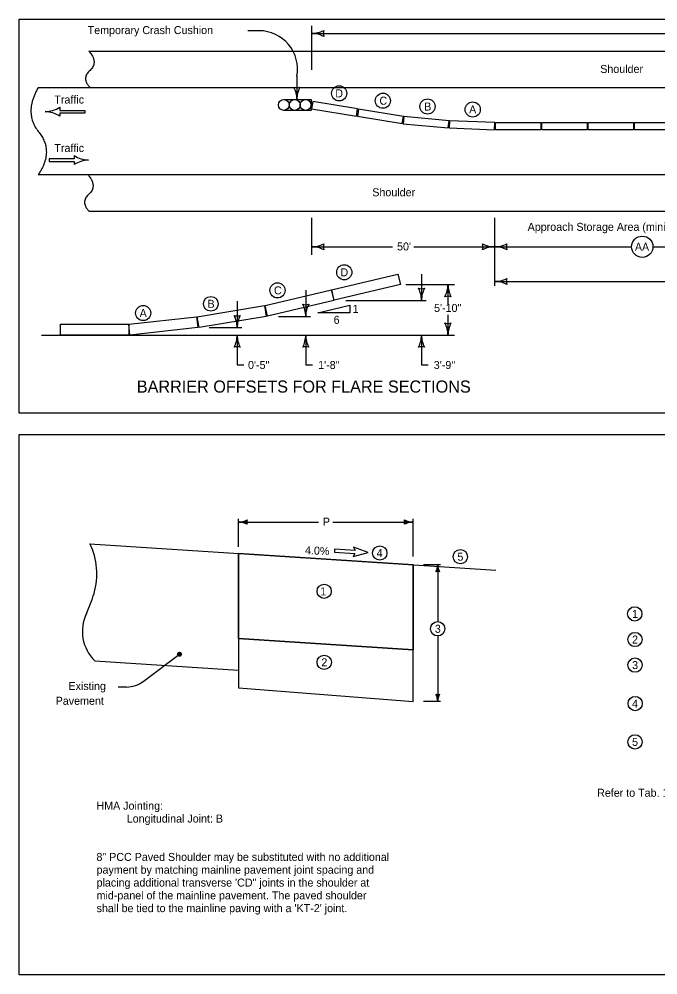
# Model space of a CAD drawing. Extents: x 6410 to 81668, y 3928 to 11667.
# Drawn here: x 13752 to 14807, y 3928 to 5504 of the extents above; entities that cross this region are included whole.
import ezdxf

# ---------------------------------------------------------------- set-up
doc = ezdxf.new("R2010")
doc.units = 0
doc.layers.add('dsnStdSection', color=7, linetype='Continuous')

msp = doc.modelspace()

# ---------------------------------------------------------------- linework, layer by layer
at = {"layer": 'dsnStdSection'}
for p, q in [((13752.2, 5504.3), (16857.2, 5504.3)), ((13752.2, 4854.3), (13752.2, 5504.3)), ((14235.1, 5493.4), (14235.1, 5420.9)), ((14148.6, 5485.1), (14129.9, 5485.1)), ((14235.1, 5480.7), (15168, 5480.7)), ((13867.5, 5451.7), (14996, 5451.7)), ((14210.8, 5410.5), (14210.8, 5371.8)), ((13783.9, 5391.7), (15026, 5391.7)), ((14189.2, 5371.8), (14234.2, 5371.8)), ((14234.2, 5371.8), (14234.2, 5353.8)), ((13795.4, 5351.6), (13795.4, 5351.6)), ((13819.3, 5359.1), (13819.3, 5353.8)), ((13819.3, 5353.8), (13860.5, 5353.8)), ((13860.5, 5349.3), (13819.3, 5349.3)), ((13819.3, 5349.3), (13819.3, 5344.1)), ((13860.5, 5353.8), (13860.5, 5349.3)), ((14234.2, 5353.8), (14189.2, 5353.8)), ((14233, 5359.5), (14234.3, 5359.2)), ((14234.8, 5355.8), (14234.8, 5355.8)), ((13842.9, 5274), (13801.7, 5274)), ((13801.7, 5274), (13801.7, 5269.5)), ((13801.7, 5269.5), (13842.9, 5269.5)), ((13842.9, 5279.2), (13842.9, 5274)), ((13842.9, 5269.5), (13842.9, 5264.2)), ((13866.8, 5271.7), (13866.8, 5271.7)), ((13783.9, 5247.7), (15026, 5247.7)), ((13867.5, 5187.7), (14996, 5187.7)), ((14235.1, 5176.4), (14235.1, 5115.2)), ((14537.3, 5176.4), (14537.3, 5064.1)), ((14235.1, 5128.7), (14368.5, 5128.7)), ((14403.8, 5128.7), (14537.3, 5128.7)), ((14537.3, 5128.7), (14763.4, 5128.7)), ((14798.7, 5128.7), (15024.8, 5128.7)), ((14416.5, 5083.8), (14416.5, 5040.3)), ((14390.6, 5066.3), (14471, 5066.3)), ((14460.2, 5066.3), (14460.2, 5032.8)), ((14537.3, 5071.5), (15128.1, 5071.5)), ((14225.4, 5057.4), (14225.4, 5013.9)), ((14112.2, 5038.8), (14112.2, 4995.3)), ((14245.5, 5019.9), (14298.1, 5032.4)), ((14291.7, 5040.3), (14424.3, 5040.3)), ((14298.1, 5032.4), (14298.1, 5019.9)), ((14298.1, 5019.9), (14245.5, 5019.9)), ((14460.2, 5016.5), (14460.2, 4983)), ((14180.4, 5013.9), (14233.1, 5013.9)), ((13789.1, 4983), (14471, 4983)), ((14066.2, 4995.3), (14119.9, 4995.3)), ((14112.2, 4983), (14112.2, 4956.1)), ((14225.4, 4983), (14225.4, 4933.7)), ((14416.5, 4983), (14416.5, 4933.7)), ((14112.2, 4956.1), (14112.2, 4933.7)), ((14112.2, 4933.7), (14123.3, 4933.7)), ((14225.4, 4933.7), (14236.5, 4933.7)), ((14416.5, 4933.7), (14427.7, 4933.7)), ((16857.2, 4854.3), (13752.2, 4854.3)), ((14114.2, 4633.9), (14114.2, 4680.1)), ((14114.2, 4674.5), (14128, 4674.5)), ((14114.2, 4674.5), (14246.5, 4674.5)), ((14270.4, 4674.5), (14402.7, 4674.5)), ((14402.7, 4674.5), (14388.8, 4674.5)), ((14402.7, 4617.8), (14402.7, 4680.1)), ((13868.8, 4638.8), (14539.1, 4595.4)), ((14420, 4604.3), (14448, 4604.3)), ((14443.3, 4604.3), (14443.3, 4592.8)), ((14443.3, 4604.3), (14443.3, 4510.3)), ((14114.2, 4482.6), (14402.7, 4463.9)), ((14443.3, 4486.7), (14443.3, 4378.7)), ((13957, 4411.7), (14017.1, 4456.7)), ((13877, 4445.5), (14114.2, 4430.2)), ((13929.6, 4402.4), (13915.5, 4402.4)), ((14443.3, 4378.7), (14443.3, 4390.1)), ((14448, 4378.7), (14420, 4378.7))]:
    msp.add_line(p, q, dxfattribs=at)
for points in [[(14311.1, 5356.3), (14237, 5368.4), (14235.1, 5356.5), (14309.1, 5344.4)], [(14386.6, 5343.9), (14312.5, 5356), (14310.6, 5344.2), (14384.6, 5332)], [(14462, 5336.6), (14387.3, 5343.8), (14386.2, 5331.8), (14460.8, 5324.7)], [(14537.7, 5333.7), (14462.8, 5336.7), (14462.3, 5324.7), (14537.3, 5321.7)], [(14538.5, 5333.7), (14613.5, 5333.7), (14613.5, 5321.7), (14538.5, 5321.7)], [(14615, 5333.7), (14690, 5333.7), (14690, 5321.7), (14615, 5321.7)], [(14691.5, 5333.7), (14766.5, 5333.7), (14766.5, 5321.7), (14691.5, 5321.7)], [(14768, 5333.7), (14843, 5333.7), (14843, 5321.7), (14768, 5321.7)], [(14268.2, 5057.9), (14377.7, 5083.8), (14381.8, 5066.3), (14272.3, 5040.4)], [(14158.4, 5031.9), (14267.8, 5057.8), (14272, 5040.3), (14162.5, 5014.4)], [(14046.3, 5013.2), (14157.3, 5031.7), (14160.2, 5013.9), (14049.2, 4995.5)], [(13820.7, 5001.1), (13933.2, 5001), (13933.2, 4983), (13820.7, 4983.1)], [(13933.2, 5000.9), (14045, 5013.2), (14047, 4995.3), (13935.2, 4983)], [(13752.2, 4818.8), (15302.9, 4818.8), (15302.9, 3927.5), (13752.2, 3927.5)], [(14114.2, 4623.2), (14402.7, 4604.3), (14402.7, 4463.9), (14114.2, 4482.6)], [(14303.5, 4617.9), (14328.4, 4624.1), (14304.3, 4633.1), (14307, 4627.9), (14273.1, 4630.1), (14272.8, 4624.9), (14306.6, 4622.8)]]:
    msp.add_lwpolyline(points, close=True, dxfattribs=at)
for points in [[(14127.8, 4672), (14127.2, 4674.5), (14127.8, 4677.1), (14124.7, 4675.6), (14119.8, 4674.5), (14125, 4673.3), (14127.3, 4672.3), (14126.8, 4674.5), (14127, 4676.2), (14124.9, 4675.2), (14122.2, 4674.5), (14125.1, 4673.7), (14126.6, 4673.2), (14126.3, 4675.4), (14124.3, 4674.5), (14125.9, 4674), (14125.9, 4674.8), (14125.2, 4674.6)], [(14389.1, 4677.1), (14389.6, 4674.5), (14389.1, 4671.9), (14392.2, 4673.4), (14397.1, 4674.5), (14391.8, 4675.7), (14389.6, 4676.8), (14390.1, 4674.5), (14389.9, 4672.9), (14391.9, 4673.8), (14394.7, 4674.5), (14391.8, 4675.4), (14390.3, 4675.9), (14390.5, 4673.7), (14392.5, 4674.5), (14391, 4675), (14390.9, 4674.3), (14391.7, 4674.5)], [(14114.2, 4623.2), (14114.2, 4401.3), (14402.7, 4378.7), (14402.7, 4604.3)], [(14441.2, 4593.1), (14443.4, 4593.5), (14445.5, 4593.1), (14444.3, 4595.6), (14443.4, 4599.7), (14442.3, 4595.3), (14441.5, 4593.4), (14443.4, 4593.9), (14444.7, 4593.7), (14443.9, 4595.4), (14443.4, 4597.6), (14442.7, 4595.3), (14442.2, 4594), (14444.1, 4594.2), (14443.4, 4595.9), (14442.9, 4594.6), (14443.6, 4594.6), (14443.4, 4595.2)], [(14019.1, 4458.3), (14018, 4458.7), (14016.4, 4459.5), (14015, 4458.6), (14014.2, 4457.4), (14013.9, 4455.7), (14015.1, 4454.7), (14016.5, 4453.7), (14018, 4454), (14019.1, 4454.9), (14019.7, 4456.9), (14018.9, 4457.9), (14017.5, 4458.7), (14015.7, 4458.9), (14014.7, 4457.8), (14014.5, 4456.1), (14015.5, 4455), (14016.9, 4454.1), (14017.7, 4454.5), (14018.7, 4455.1), (14019.2, 4456.6), (14018.3, 4457.4), (14017.1, 4458.3), (14015.9, 4458.4), (14015.3, 4457.1), (14015.4, 4455.8), (14016.4, 4454.8), (14017.2, 4455), (14018.1, 4455.3), (14018.4, 4456.6), (14017.8, 4457.5), (14016.8, 4457.8), (14016.1, 4457.1), (14015.9, 4456.3), (14016.4, 4455.4), (14017, 4455.4), (14017.5, 4455.6), (14017.8, 4456.5), (14017.4, 4457.1), (14016.7, 4457.3), (14016.4, 4456.8), (14016.5, 4456.2), (14017, 4455.8), (14017.3, 4456.1), (14017.1, 4456.7)], [(14445.5, 4389.9), (14443.3, 4389.5), (14441.2, 4389.9), (14442.4, 4387.4), (14443.3, 4383.3), (14444.4, 4387.7), (14445.2, 4389.5), (14443.3, 4389.1), (14442, 4389.2), (14442.8, 4387.6), (14443.3, 4385.3), (14444, 4387.7), (14444.5, 4389), (14442.6, 4388.7), (14443.3, 4387.1), (14443.7, 4388.4), (14443.1, 4388.4), (14443.3, 4387.8)]]:
    msp.add_lwpolyline(points, dxfattribs=at)
for centre, radius in [((14280.6, 5381.8), 12.5), ((14352.8, 5369.7), 12.5), ((14189.2, 5362.8), 9), ((14189.2, 5362.8), 9), ((14207.2, 5362.8), 9), ((14207.2, 5362.8), 9), ((14225.2, 5362.8), 9), ((14225.2, 5362.8), 9), ((14426.5, 5360.1), 12.5), ((14501.1, 5355.2), 12.5), ((14781, 5128.7), 17.6), ((14289, 5086.6), 12.5), ((14178.7, 5056.8), 12.5), ((14068.7, 5034.6), 12.2), ((13957.1, 5019.4), 12.5), ((14347.7, 4623.5), 11.8), ((14480.7, 4617.4), 11.8), ((14255.8, 4560.4), 11.8), ((14768.6, 4523.1), 11.8), ((14443.3, 4498.5), 11.8), ((14768.9, 4480.8), 11.8), ((14016.9, 4456.5), 3.15), ((14255.9, 4443.2), 11.8), ((14769.1, 4438.6), 11.8), ((14769.3, 4375.2), 11.8), ((14769, 4311.9), 11.8)]:
    msp.add_circle(centre, radius, dxfattribs=at)
for centre, radius, start, end in [((14148.6, 5421.8), 63.3, 349.6463, 90), ((14235.1, 5523.2), 42.5, 270, 298.0725), ((14235.1, 5438.2), 42.5, 61.9275, 90), ((14270.7, 5480.7), 16.4, 162.2666, 197.7334), ((14210.8, 5407.5), 16.4, 252.2666, 287.7333), ((14168.3, 5371.8), 42.5, 360, 28.0725), ((14253.3, 5371.8), 42.5, 151.9275, 180), ((13793.4, 5399.9), 48.4, 272.352, 302.382), ((13793.4, 5303.3), 48.4, 57.618, 87.648), ((13868.8, 5320.1), 48.4, 237.618, 267.648), ((13868.8, 5223.4), 48.4, 92.352, 122.382), ((14235.1, 5171.2), 42.5, 270, 298.0725), ((14235.1, 5086.2), 42.5, 61.9275, 90), ((14270.7, 5128.7), 16.4, 162.2666, 197.7334), ((14501.6, 5128.7), 16.4, 342.2666, 17.7333), ((14537.3, 5171.2), 42.5, 241.9275, 270), ((14537.3, 5086.2), 42.5, 90, 118.0725), ((14537.3, 5171.2), 42.5, 270, 298.0725), ((14537.3, 5086.2), 42.5, 61.9275, 90), ((14572.9, 5128.7), 16.4, 162.2666, 197.7334), ((14417.7, 5066.3), 42.5, 331.9275, 360), ((14502.7, 5066.3), 42.5, 180, 208.0725), ((14537.3, 5114), 42.5, 270, 298.0725), ((14537.3, 5029), 42.5, 61.9275, 90), ((14572.9, 5071.5), 16.4, 162.2666, 197.7334), ((14416.5, 5075.9), 16.4, 252.2666, 287.7333), ((14374, 5040.3), 42.5, 360, 28.0725), ((14459, 5040.3), 42.5, 151.9275, 180), ((14460.2, 5030.7), 16.4, 72.2666, 107.7334), ((14225.4, 5049.5), 16.4, 252.2666, 287.7333), ((14182.9, 5013.9), 42.5, 360, 28.0725), ((14267.9, 5013.9), 42.5, 151.9275, 180), ((14112.2, 5031), 16.4, 252.2666, 287.7333), ((14069.7, 4995.3), 42.5, 360, 28.0725), ((14154.7, 4995.3), 42.5, 151.9275, 180), ((14460.2, 5018.6), 16.4, 252.2666, 287.7333), ((14417.7, 4983), 42.5, 360, 28.0725), ((14502.7, 4983), 42.5, 151.9275, 180), ((14069.7, 4983), 42.5, 331.9275, 360), ((14154.7, 4983), 42.5, 180, 208.0725), ((14182.9, 4983), 42.5, 331.9275, 360), ((14267.9, 4983), 42.5, 180, 208.0725), ((14374, 4983), 42.5, 331.9275, 360), ((14459, 4983), 42.5, 180, 208.0725), ((14112.2, 4947.4), 16.4, 72.2666, 107.7334), ((14225.4, 4947.4), 16.4, 72.2666, 107.7334), ((14416.5, 4947.4), 16.4, 72.2666, 107.7334), ((14114.2, 4705.1), 30.6, 270, 298.0725), ((14114.2, 4643.9), 30.6, 61.9275, 90), ((14139.9, 4674.5), 11.8, 162.2666, 197.7334), ((14377, 4674.5), 11.8, 342.2666, 17.7334), ((14402.7, 4705.1), 30.6, 241.9275, 270), ((14402.7, 4643.9), 30.6, 90, 118.0725), ((13767.6, 4588.7), 113, 343.6708, 26.3373), ((14418.1, 4604.3), 25.2, 331.9275, 360), ((14468.6, 4604.3), 25.2, 180, 208.0725), ((14443.3, 4583.1), 9.75, 72.2666, 107.7334), ((13663.5, 4619.2), 221.4, 334.4332, 343.6708), ((13924.8, 4494.2), 68.2, 154.4332, 225.5564), ((13929.6, 4447.4), 45, 270, 307.6187), ((14443.3, 4399.9), 9.75, 252.2666, 287.7334), ((14418.1, 4378.7), 25.2, 360, 28.0725), ((14468.6, 4378.7), 25.2, 151.9275, 180)]:
    msp.add_arc(centre, radius, start, end, dxfattribs=at)
for points in [[(13867.5, 5451.7), (13883.5, 5432.4), (13854.6, 5406.8), (13869.1, 5391.8)], [(13783.9, 5391.7), (13759.2, 5349.1), (13810, 5286.9), (13783.9, 5247.7)], [(13865.9, 5247.7), (13881.9, 5228.4), (13853, 5202.8), (13867.5, 5187.7)]]:
    msp.add_open_spline(points, degree=2, dxfattribs=at)

# ---------------------------------------------------------------- texts
for s, height, p in [('Temporary Crash Cushion', 13.2, (13865.4, 5479.6)), ('Shoulder', 13.2, (14711.6, 5415.5)), ('Traffic', 13.2, (13810.4, 5365)), ('D', 13.2, (14274.2, 5375.2)), ('C', 13.2, (14347.1, 5363.1)), ('B', 13.2, (14421.1, 5353.5)), ('A', 13.2, (14495.2, 5348.6)), ('Traffic', 13.2, (13810.4, 5285.1)), ('Shoulder', 13.2, (14335.3, 5212)), ("Approach Storage Area (minimum 20')", 13.2, (14591.8, 5155)), ("50'", 13.2, (14376.2, 5122.7)), ('AA', 13.2, (14768.8, 5122.1)), ('D', 13.2, (14282.7, 5080)), ('C', 13.2, (14173, 5050.2)), ('B', 13.2, (14063.2, 5028)), ('1', 13.2, (14302.7, 5019.7)), ("5'-10''", 13.2, (14437.3, 5021.2)), ('A', 13.2, (13951.2, 5012.8)), ('6', 13.2, (14271.5, 5001.6)), ("0'-5''", 13.2, (14130.1, 4927.1)), ("1'-8''", 13.2, (14245.9, 4927.1)), ("3'-9''", 13.2, (14436.8, 4927.1)), ('BARRIER OFFSETS FOR FLARE SECTIONS', 20, (13946.5, 4888.1)), ('P', 13.2, (14253.8, 4668.5)), ('4', 13.2, (14342.5, 4616.9)), ('5', 13.2, (14475.8, 4610.8)), ('1', 13.2, (14249.2, 4553.5)), ('1', 13.2, (14764.2, 4516.5)), ('3', 13.2, (14438.5, 4491.9)), ('2', 13.2, (14764.2, 4474.2)), ('2', 13.2, (14251.2, 4436.6)), ('3', 13.2, (14764.2, 4432)), ('Existing', 13.2, (13833.7, 4397.5)), ('Pavement', 13.2, (13812.6, 4373.1)), ('4', 13.2, (14764.2, 4368.6)), ('5', 13.2, (14764.2, 4305.3)), ('Refer to Tab. 112-9 for P width and Shoulder quantities', 13.2, (14706.5, 4221.4)), ('HMA Jointing:', 13.2, (13879.9, 4200)), ('Longitudinal Joint: B', 13.2, (13929.9, 4178.8)), ('8" PCC Paved Shoulder may be substituted with no additional ', 13.2, (13879.9, 4115.5)), ('payment by matching mainline pavement joint spacing and ', 13.2, (13880.1, 4094.4)), ('placing additional transverse \'CD" joints in the shoulder at ', 13.2, (13880.1, 4073.2)), ('mid-panel of the mainline pavement. The paved shoulder ', 13.2, (13880.1, 4052.1)), ("shall be tied to the mainline paving with a 'KT-2' joint.", 13.2, (13880.1, 4031))]:
    msp.add_text(s, height=height, dxfattribs=at).set_placement(p)
msp.add_text('4.0%', height=13.2, rotation=357.4961, dxfattribs=at).set_placement((14224, 4621.7))

doc.saveas('drawing.dxf')
